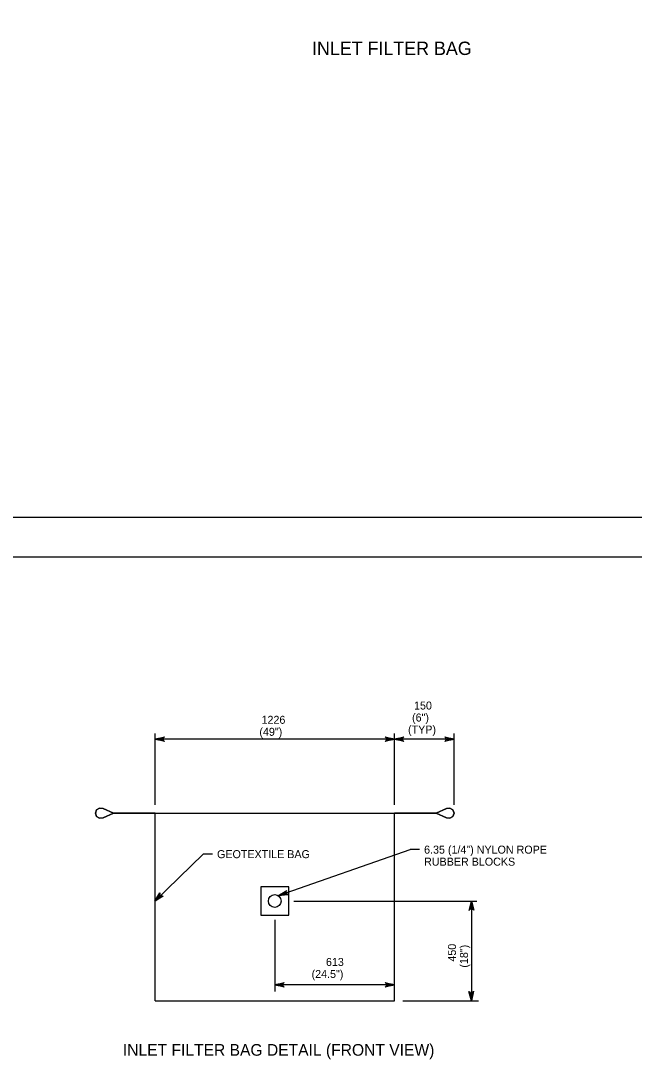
# Model space of a CAD drawing. Extents: x 636183 to 639890, y 299162 to 300538.
# Drawn here: x 636691.5 to 636921.1, y 299162.4 to 299551.4 of the extents above; entities that cross this region are included whole.
import ezdxf

# ---------------------------------------------------------------- set-up
doc = ezdxf.new("R2010")
doc.units = 0
for name, color, linetype in [('1', 7, 'Continuous'), ('Default', 7, 'Continuous'), ('PLT-BNDY', 7, 'Continuous')]:
    doc.layers.add(name, color=color, linetype=linetype)

msp = doc.modelspace()

# ---------------------------------------------------------------- linework, layer by layer
at = {"layer": '1'}
msp.add_lwpolyline([(637287.91, 299365.45), (637287.91, 299929.45), (636501.91, 299929.45), (636501.91, 299365.45), (637287.91, 299365.45), (637287.91, 299391.81), (637087.91, 299391.81), (637087.91, 299456.49), (637287.91, 299456.49), (637287.91, 299485.45), (637087.91, 299485.45), (637087.91, 299365.45), (637166.72, 299365.45), (637166.72, 299391.81), (637166.72, 299365.45), (637243.72, 299365.45), (637243.72, 299391.81), (637243.72, 299379.49), (637287.91, 299379.49)], dxfattribs=at)
at = {"layer": 'Default'}
for p, q in [((636741.83, 299257.73), (636741.83, 299284.38)), ((636831.39, 299257.73), (636831.39, 299284.38)), ((636853.71, 299257.73), (636853.71, 299284.38)), ((636719.93, 299255.82), (636719.51, 299254.56)), ((636719.93, 299255.82), (636719.51, 299254.56)), ((636719.51, 299254.56), (636719.93, 299255.82)), ((636719.93, 299255.82), (636719.51, 299254.56)), ((636719.51, 299254.56), (636719.93, 299255.82)), ((636719.51, 299254.56), (636719.93, 299255.82)), ((636721.05, 299256.48), (636719.93, 299255.82)), ((636721.05, 299256.48), (636719.93, 299255.82)), ((636719.93, 299255.82), (636721.05, 299256.48)), ((636721.05, 299256.48), (636719.93, 299255.82)), ((636719.93, 299255.82), (636721.05, 299256.48)), ((636719.93, 299255.82), (636721.05, 299256.48)), ((636719.93, 299255.82), (636719.93, 299255.82)), ((636719.93, 299255.82), (636719.93, 299255.82)), ((636719.93, 299255.82), (636719.93, 299255.82)), ((636721.05, 299256.48), (636721.05, 299256.48)), ((636721.05, 299256.48), (636721.05, 299256.48)), ((636721.05, 299256.48), (636721.05, 299256.48)), ((636722.35, 299256.34), (636721.05, 299256.48)), ((636722.35, 299256.34), (636721.05, 299256.48)), ((636721.05, 299256.48), (636722.35, 299256.34)), ((636722.35, 299256.34), (636721.05, 299256.48)), ((636721.05, 299256.48), (636722.35, 299256.34)), ((636721.05, 299256.48), (636722.35, 299256.34)), ((636722.35, 299256.34), (636722.35, 299256.34)), ((636722.35, 299256.34), (636722.35, 299256.34)), ((636722.35, 299256.34), (636722.35, 299256.34)), ((636722.35, 299256.34), (636726.23, 299254.53)), ((636726.23, 299254.53), (636722.35, 299256.34)), ((636726.23, 299254.53), (636722.35, 299256.34)), ((636726.23, 299254.53), (636722.35, 299256.34)), ((636722.35, 299256.34), (636726.23, 299254.53)), ((636722.35, 299256.34), (636726.23, 299254.53)), ((636850.88, 299256.34), (636846.99, 299254.53)), ((636846.99, 299254.53), (636850.88, 299256.34)), ((636846.99, 299254.53), (636850.88, 299256.34)), ((636846.99, 299254.53), (636850.88, 299256.34)), ((636850.88, 299256.34), (636846.99, 299254.53)), ((636850.88, 299256.34), (636846.99, 299254.53)), ((636850.88, 299256.34), (636852.17, 299256.48)), ((636850.88, 299256.34), (636852.17, 299256.48)), ((636852.17, 299256.48), (636850.88, 299256.34)), ((636850.88, 299256.34), (636852.17, 299256.48)), ((636852.17, 299256.48), (636850.88, 299256.34)), ((636852.17, 299256.48), (636850.88, 299256.34)), ((636850.88, 299256.34), (636850.88, 299256.34)), ((636850.88, 299256.34), (636850.88, 299256.34)), ((636850.88, 299256.34), (636850.88, 299256.34)), ((636852.17, 299256.48), (636852.17, 299256.48)), ((636852.17, 299256.48), (636853.29, 299255.82)), ((636852.17, 299256.48), (636852.17, 299256.48)), ((636852.17, 299256.48), (636852.17, 299256.48)), ((636852.17, 299256.48), (636853.29, 299255.82)), ((636853.29, 299255.82), (636852.17, 299256.48)), ((636852.17, 299256.48), (636853.29, 299255.82)), ((636853.29, 299255.82), (636852.17, 299256.48)), ((636853.29, 299255.82), (636852.17, 299256.48)), ((636853.29, 299255.82), (636853.29, 299255.82)), ((636853.29, 299255.82), (636853.29, 299255.82)), ((636853.29, 299255.82), (636853.29, 299255.82)), ((636853.29, 299255.82), (636853.71, 299254.56)), ((636853.29, 299255.82), (636853.71, 299254.56)), ((636853.71, 299254.56), (636853.29, 299255.82)), ((636853.29, 299255.82), (636853.71, 299254.56)), ((636853.71, 299254.56), (636853.29, 299255.82)), ((636853.71, 299254.56), (636853.29, 299255.82)), ((636719.51, 299254.56), (636719.51, 299254.56)), ((636719.51, 299254.56), (636719.51, 299254.56)), ((636719.51, 299254.56), (636719.51, 299254.56)), ((636719.51, 299254.56), (636719.93, 299253.34)), ((636719.51, 299254.56), (636719.93, 299253.34)), ((636719.93, 299253.34), (636719.51, 299254.56)), ((636719.51, 299254.56), (636719.93, 299253.34)), ((636719.93, 299253.34), (636719.51, 299254.56)), ((636719.93, 299253.34), (636719.51, 299254.56)), ((636719.93, 299253.34), (636719.93, 299253.34)), ((636719.93, 299253.34), (636719.93, 299253.34)), ((636719.93, 299253.34), (636719.93, 299253.34)), ((636719.93, 299253.34), (636721.05, 299252.64)), ((636719.93, 299253.34), (636721.05, 299252.64)), ((636721.05, 299252.64), (636719.93, 299253.34)), ((636719.93, 299253.34), (636721.05, 299252.64)), ((636721.05, 299252.64), (636719.93, 299253.34)), ((636721.05, 299252.64), (636719.93, 299253.34)), ((636721.05, 299252.64), (636722.35, 299252.78)), ((636721.05, 299252.64), (636722.35, 299252.78)), ((636722.35, 299252.78), (636721.05, 299252.64)), ((636721.05, 299252.64), (636722.35, 299252.78)), ((636722.35, 299252.78), (636721.05, 299252.64)), ((636722.35, 299252.78), (636721.05, 299252.64)), ((636721.05, 299252.64), (636721.05, 299252.64)), ((636721.05, 299252.64), (636721.05, 299252.64)), ((636721.05, 299252.64), (636721.05, 299252.64)), ((636722.35, 299252.78), (636726.23, 299254.53)), ((636722.35, 299252.78), (636726.23, 299254.53)), ((636726.23, 299254.53), (636722.35, 299252.78)), ((636722.35, 299252.78), (636726.23, 299254.53)), ((636726.23, 299254.53), (636722.35, 299252.78)), ((636726.23, 299254.53), (636722.35, 299252.78)), ((636722.35, 299252.78), (636722.35, 299252.78)), ((636722.35, 299252.78), (636722.35, 299252.78)), ((636722.35, 299252.78), (636722.35, 299252.78)), ((636726.23, 299254.53), (636726.23, 299254.53)), ((636726.23, 299254.53), (636726.23, 299254.53)), ((636726.23, 299254.53), (636726.23, 299254.53)), ((636726.23, 299254.53), (636726.23, 299254.53)), ((636726.23, 299254.53), (636727.35, 299254.53)), ((636726.23, 299254.53), (636726.23, 299254.53)), ((636726.23, 299254.53), (636726.23, 299254.53)), ((636727.35, 299254.53), (636726.23, 299254.53)), ((636726.23, 299254.53), (636727.35, 299254.53)), ((636727.35, 299254.53), (636726.23, 299254.53)), ((636741.83, 299254.53), (636726.23, 299254.53)), ((636726.23, 299254.53), (636741.83, 299254.53)), ((636727.35, 299254.53), (636728.43, 299254.53)), ((636728.43, 299254.53), (636727.35, 299254.53)), ((636727.35, 299254.53), (636728.43, 299254.53)), ((636728.43, 299254.53), (636727.35, 299254.53)), ((636728.43, 299254.53), (636729.52, 299254.53)), ((636729.52, 299254.53), (636728.43, 299254.53)), ((636728.43, 299254.53), (636729.52, 299254.53)), ((636729.52, 299254.53), (636728.43, 299254.53)), ((636729.52, 299254.53), (636730.5, 299254.53)), ((636730.5, 299254.53), (636729.52, 299254.53)), ((636729.52, 299254.53), (636730.5, 299254.53)), ((636730.5, 299254.53), (636729.52, 299254.53)), ((636730.5, 299254.53), (636731.48, 299254.53)), ((636731.48, 299254.53), (636730.5, 299254.53)), ((636730.5, 299254.53), (636731.48, 299254.53)), ((636731.48, 299254.53), (636730.5, 299254.53)), ((636731.48, 299254.53), (636732.35, 299254.53)), ((636732.35, 299254.53), (636731.48, 299254.53)), ((636731.48, 299254.53), (636732.35, 299254.53)), ((636732.35, 299254.53), (636731.48, 299254.53)), ((636732.35, 299254.53), (636733.12, 299254.53)), ((636733.12, 299254.53), (636732.35, 299254.53)), ((636732.35, 299254.53), (636733.12, 299254.53)), ((636733.12, 299254.53), (636732.35, 299254.53)), ((636733.12, 299254.53), (636733.82, 299254.53)), ((636733.82, 299254.53), (636733.12, 299254.53)), ((636733.12, 299254.53), (636733.82, 299254.53)), ((636733.82, 299254.53), (636733.12, 299254.53)), ((636733.82, 299254.53), (636734.38, 299254.53)), ((636734.38, 299254.53), (636733.82, 299254.53)), ((636733.82, 299254.53), (636734.38, 299254.53)), ((636734.38, 299254.53), (636733.82, 299254.53)), ((636734.38, 299254.53), (636734.83, 299254.53)), ((636734.83, 299254.53), (636734.38, 299254.53)), ((636734.38, 299254.53), (636734.83, 299254.53)), ((636734.83, 299254.53), (636734.38, 299254.53)), ((636734.83, 299254.53), (636735.15, 299254.53)), ((636735.15, 299254.53), (636734.83, 299254.53)), ((636734.83, 299254.53), (636735.15, 299254.53)), ((636735.15, 299254.53), (636734.83, 299254.53)), ((636735.15, 299254.53), (636735.36, 299254.53)), ((636735.36, 299254.53), (636735.15, 299254.53)), ((636735.15, 299254.53), (636735.36, 299254.53)), ((636735.36, 299254.53), (636735.15, 299254.53)), ((636735.36, 299254.53), (636735.43, 299254.53)), ((636735.43, 299254.53), (636735.36, 299254.53)), ((636735.36, 299254.53), (636735.43, 299254.53)), ((636735.43, 299254.53), (636735.36, 299254.53)), ((636741.83, 299254.53), (636831.39, 299254.53)), ((636741.83, 299184.33), (636741.83, 299254.53)), ((636831.39, 299184.33), (636831.39, 299254.53)), ((636831.39, 299254.53), (636846.99, 299254.53)), ((636846.99, 299254.53), (636831.39, 299254.53)), ((636837.86, 299254.53), (636837.79, 299254.53)), ((636837.79, 299254.53), (636837.86, 299254.53)), ((636837.86, 299254.53), (636837.79, 299254.53)), ((636837.79, 299254.53), (636837.86, 299254.53)), ((636838.07, 299254.53), (636837.86, 299254.53)), ((636837.86, 299254.53), (636838.07, 299254.53)), ((636838.07, 299254.53), (636837.86, 299254.53)), ((636837.86, 299254.53), (636838.07, 299254.53)), ((636838.39, 299254.53), (636838.07, 299254.53)), ((636838.07, 299254.53), (636838.39, 299254.53)), ((636838.39, 299254.53), (636838.07, 299254.53)), ((636838.07, 299254.53), (636838.39, 299254.53)), ((636838.84, 299254.53), (636838.39, 299254.53)), ((636838.39, 299254.53), (636838.84, 299254.53)), ((636838.84, 299254.53), (636838.39, 299254.53)), ((636838.39, 299254.53), (636838.84, 299254.53)), ((636839.4, 299254.53), (636838.84, 299254.53)), ((636838.84, 299254.53), (636839.4, 299254.53)), ((636839.4, 299254.53), (636838.84, 299254.53)), ((636838.84, 299254.53), (636839.4, 299254.53)), ((636840.1, 299254.53), (636839.4, 299254.53)), ((636839.4, 299254.53), (636840.1, 299254.53)), ((636840.1, 299254.53), (636839.4, 299254.53)), ((636839.4, 299254.53), (636840.1, 299254.53)), ((636840.87, 299254.53), (636840.1, 299254.53)), ((636840.1, 299254.53), (636840.87, 299254.53)), ((636840.87, 299254.53), (636840.1, 299254.53)), ((636840.1, 299254.53), (636840.87, 299254.53)), ((636841.75, 299254.53), (636840.87, 299254.53)), ((636840.87, 299254.53), (636841.75, 299254.53)), ((636841.75, 299254.53), (636840.87, 299254.53)), ((636840.87, 299254.53), (636841.75, 299254.53)), ((636842.73, 299254.53), (636841.75, 299254.53)), ((636841.75, 299254.53), (636842.73, 299254.53)), ((636842.73, 299254.53), (636841.75, 299254.53)), ((636841.75, 299254.53), (636842.73, 299254.53)), ((636843.71, 299254.53), (636842.73, 299254.53)), ((636842.73, 299254.53), (636843.71, 299254.53)), ((636843.71, 299254.53), (636842.73, 299254.53)), ((636842.73, 299254.53), (636843.71, 299254.53)), ((636844.79, 299254.53), (636843.71, 299254.53)), ((636843.71, 299254.53), (636844.79, 299254.53)), ((636844.79, 299254.53), (636843.71, 299254.53)), ((636843.71, 299254.53), (636844.79, 299254.53)), ((636845.87, 299254.53), (636844.79, 299254.53)), ((636844.79, 299254.53), (636845.87, 299254.53)), ((636845.87, 299254.53), (636844.79, 299254.53)), ((636844.79, 299254.53), (636845.87, 299254.53)), ((636846.99, 299254.53), (636845.87, 299254.53)), ((636845.87, 299254.53), (636846.99, 299254.53)), ((636846.99, 299254.53), (636845.87, 299254.53)), ((636845.87, 299254.53), (636846.99, 299254.53)), ((636850.88, 299252.78), (636846.99, 299254.53)), ((636850.88, 299252.78), (636846.99, 299254.53)), ((636846.99, 299254.53), (636850.88, 299252.78)), ((636846.99, 299254.53), (636846.99, 299254.53)), ((636846.99, 299254.53), (636846.99, 299254.53)), ((636846.99, 299254.53), (636846.99, 299254.53)), ((636846.99, 299254.53), (636846.99, 299254.53)), ((636846.99, 299254.53), (636846.99, 299254.53)), ((636846.99, 299254.53), (636846.99, 299254.53)), ((636850.88, 299252.78), (636846.99, 299254.53)), ((636846.99, 299254.53), (636850.88, 299252.78)), ((636846.99, 299254.53), (636850.88, 299252.78)), ((636852.17, 299252.64), (636850.88, 299252.78)), ((636852.17, 299252.64), (636850.88, 299252.78)), ((636850.88, 299252.78), (636852.17, 299252.64)), ((636852.17, 299252.64), (636850.88, 299252.78)), ((636850.88, 299252.78), (636850.88, 299252.78)), ((636850.88, 299252.78), (636850.88, 299252.78)), ((636850.88, 299252.78), (636850.88, 299252.78)), ((636850.88, 299252.78), (636852.17, 299252.64)), ((636850.88, 299252.78), (636852.17, 299252.64)), ((636853.29, 299253.34), (636852.17, 299252.64)), ((636853.29, 299253.34), (636852.17, 299252.64)), ((636852.17, 299252.64), (636853.29, 299253.34)), ((636853.29, 299253.34), (636852.17, 299252.64)), ((636852.17, 299252.64), (636853.29, 299253.34)), ((636852.17, 299252.64), (636853.29, 299253.34)), ((636852.17, 299252.64), (636852.17, 299252.64)), ((636852.17, 299252.64), (636852.17, 299252.64)), ((636852.17, 299252.64), (636852.17, 299252.64)), ((636853.71, 299254.56), (636853.29, 299253.34)), ((636853.71, 299254.56), (636853.29, 299253.34)), ((636853.29, 299253.34), (636853.71, 299254.56)), ((636853.71, 299254.56), (636853.29, 299253.34)), ((636853.29, 299253.34), (636853.71, 299254.56)), ((636853.29, 299253.34), (636853.71, 299254.56)), ((636853.29, 299253.34), (636853.29, 299253.34)), ((636853.29, 299253.34), (636853.29, 299253.34)), ((636853.29, 299253.34), (636853.29, 299253.34)), ((636853.71, 299254.56), (636853.71, 299254.56)), ((636853.71, 299254.56), (636853.71, 299254.56)), ((636853.71, 299254.56), (636853.71, 299254.56)), ((636788.04, 299223.69), (636837.24, 299240.9)), ((636840.74, 299240.9), (636837.24, 299240.9)), ((636741.75, 299221.58), (636759.74, 299239.21)), ((636763.24, 299239.21), (636759.74, 299239.21)), ((636793.7, 299221.66), (636862.29, 299221.66)), ((636786.61, 299214.62), (636786.61, 299187.8)), ((636741.83, 299184.33), (636831.39, 299184.33)), ((636834.59, 299184.33), (636862.85, 299184.33))]:
    msp.add_line(p, q, dxfattribs=at)
for points in [[(636745.06, 299281.61), (636745.33, 299281.39), (636741.83, 299282.25), (636745.06, 299281.61), (636744.86, 299281.98), (636741.83, 299282.25), (636744.86, 299282.51), (636745.04, 299282.88), (636741.83, 299282.25), (636745.32, 299283.14), (636745.04, 299282.88)], [(636828.16, 299282.89), (636827.89, 299283.11), (636831.39, 299282.25), (636828.16, 299282.89), (636828.36, 299282.51), (636831.39, 299282.25), (636828.36, 299281.99), (636828.18, 299281.61), (636831.39, 299282.25), (636827.9, 299281.36), (636828.18, 299281.61)], [(636834.63, 299281.61), (636834.89, 299281.39), (636831.39, 299282.25), (636834.63, 299281.61), (636834.43, 299281.98), (636831.39, 299282.25), (636834.42, 299282.51), (636834.61, 299282.88), (636831.39, 299282.25), (636834.89, 299283.14), (636834.61, 299282.88)], [(636850.48, 299282.89), (636850.21, 299283.11), (636853.71, 299282.25), (636850.48, 299282.89), (636850.67, 299282.51), (636853.71, 299282.25), (636850.68, 299281.99), (636850.5, 299281.61), (636853.71, 299282.25), (636850.21, 299281.36), (636850.5, 299281.61)], [(636831.39, 299282.25), (636741.83, 299282.25)], [(636853.71, 299282.25), (636831.39, 299282.25)], [(636744.47, 299223.43), (636744.82, 299223.47), (636741.75, 299221.58), (636744.47, 299223.43), (636744.07, 299223.55), (636741.75, 299221.58), (636743.69, 299223.92), (636743.55, 299224.31), (636741.75, 299221.58), (636743.57, 299224.69), (636743.55, 299224.31)], [(636791.31, 299224.09), (636791.64, 299223.97), (636788.04, 299223.69), (636791.31, 299224.09), (636791.01, 299224.39), (636788.04, 299223.69), (636790.84, 299224.88), (636790.9, 299225.3), (636788.04, 299223.69), (636791.09, 299225.63), (636790.9, 299225.3)], [(636859.54, 299218.43), (636859.32, 299218.16), (636860.18, 299221.66), (636859.54, 299218.43), (636859.92, 299218.63), (636860.18, 299221.66), (636860.44, 299218.63), (636860.82, 299218.45), (636860.18, 299221.66), (636861.07, 299218.17), (636860.82, 299218.45)], [(636860.18, 299221.66), (636860.18, 299184.33)], [(636789.84, 299189.59), (636790.11, 299189.37), (636786.61, 299190.23), (636789.84, 299189.59), (636789.65, 299189.97), (636786.61, 299190.23), (636789.64, 299190.49), (636789.82, 299190.87), (636786.61, 299190.23), (636790.11, 299191.12), (636789.82, 299190.87)], [(636831.39, 299190.23), (636786.61, 299190.23)], [(636828.16, 299190.87), (636827.89, 299191.09), (636831.39, 299190.23), (636828.16, 299190.87), (636828.36, 299190.5), (636831.39, 299190.23), (636828.36, 299189.97), (636828.18, 299189.6), (636831.39, 299190.23), (636827.9, 299189.34), (636828.18, 299189.6)], [(636860.82, 299187.56), (636861.04, 299187.83), (636860.18, 299184.33), (636860.82, 299187.56), (636860.45, 299187.36), (636860.18, 299184.33), (636859.92, 299187.36), (636859.55, 299187.54), (636860.18, 299184.33), (636859.29, 299187.82), (636859.55, 299187.54)]]:
    msp.add_lwpolyline(points, dxfattribs=at)
msp.add_lwpolyline([(636781.34, 299216.39), (636791.88, 299216.39), (636791.88, 299226.93), (636781.34, 299226.93)], close=True, dxfattribs=at)
msp.add_circle((636786.61, 299221.66), 2.38, dxfattribs=at)
at = {"layer": 'PLT-BNDY'}
msp.add_lwpolyline([(636461.91, 299944.45), (637302.91, 299944.45), (637302.91, 299350.45), (636461.91, 299350.45)], close=True, dxfattribs=at)

# ---------------------------------------------------------------- texts
at = {"layer": 'Default'}
for s, height, p in [('INLET FILTER BAG', 4.9967, (636800.53, 299538.54)), ('150', 2.998, (636838.73, 299293.38)), ('1226', 2.998, (636781.64, 299288.03)), ('(6")', 2.998, (636837.98, 299288.88)), ('(49")', 2.998, (636780.84, 299283.53)), ('(TYP)', 2.998, (636836.48, 299284.39)), ('GEOTEXTILE BAG', 2.998, (636764.99, 299237.71)), ('6.35 (1/4") NYLON ROPE', 2.998, (636842.49, 299239.4)), ('RUBBER BLOCKS', 2.998, (636842.49, 299234.9)), ('613', 2.998, (636805.76, 299197.33)), ('(24.5")', 2.998, (636800.38, 299192.83)), ('INLET FILTER BAG DETAIL (FRONT VIEW)', 4.3721, (636729.73, 299163.71))]:
    msp.add_text(s, height=height, dxfattribs=at).set_placement(p)
for s, p in [('450', (636854.42, 299198.96)), ('(18")', (636858.91, 299196.71))]:
    msp.add_text(s, height=2.998, rotation=90, dxfattribs=at).set_placement(p)

doc.saveas('drawing.dxf')
